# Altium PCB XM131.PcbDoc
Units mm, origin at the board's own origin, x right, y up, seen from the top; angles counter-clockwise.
Board outline 18.6 x 15 mm, 4 copper layers (Layer 1, Layer 2, Layer 3, Layer 4), stack 1.035 mm thick; 23 components, 34 nets, 164 pads, 93 vias.
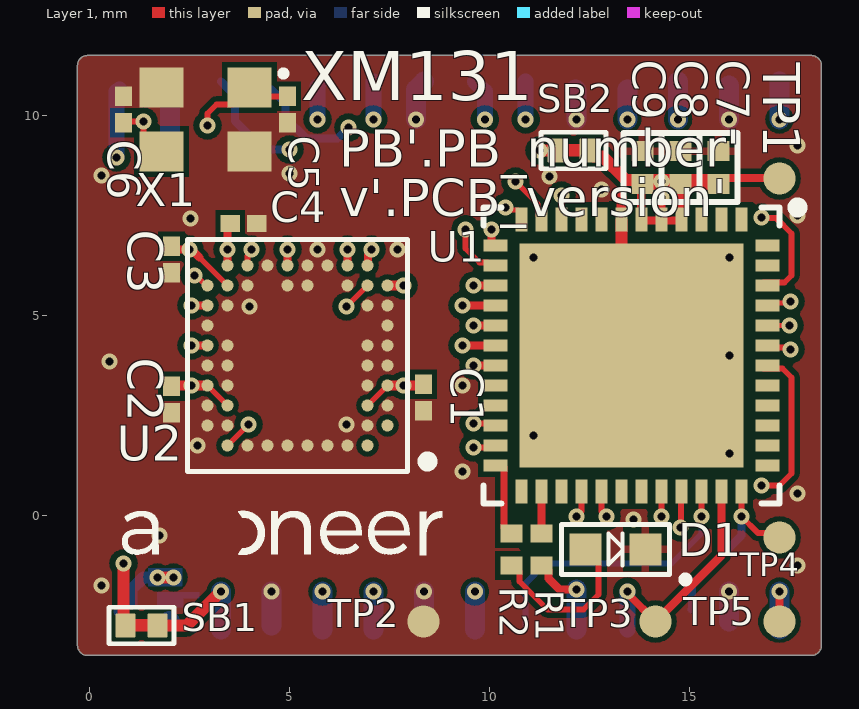
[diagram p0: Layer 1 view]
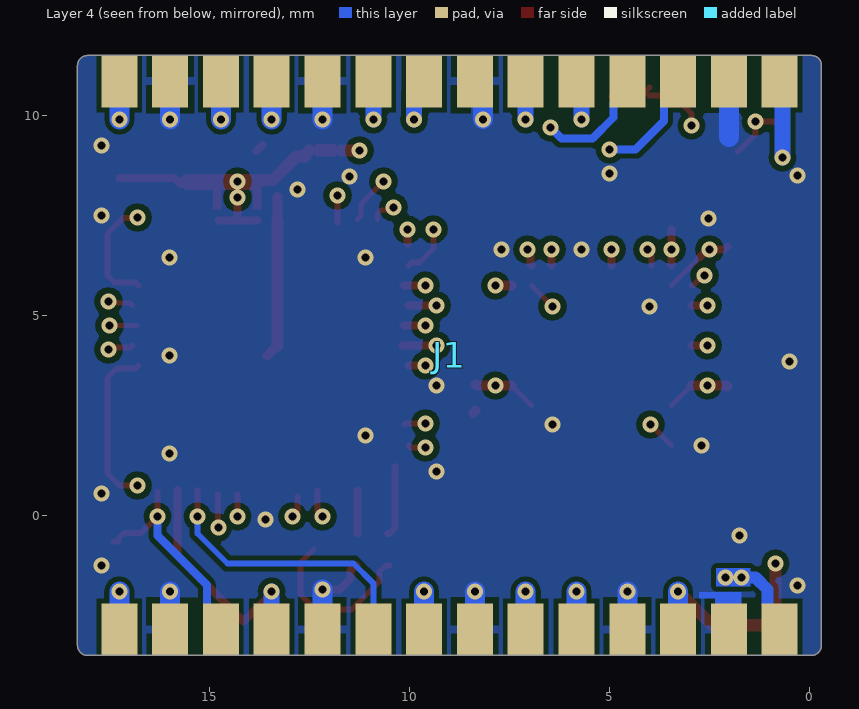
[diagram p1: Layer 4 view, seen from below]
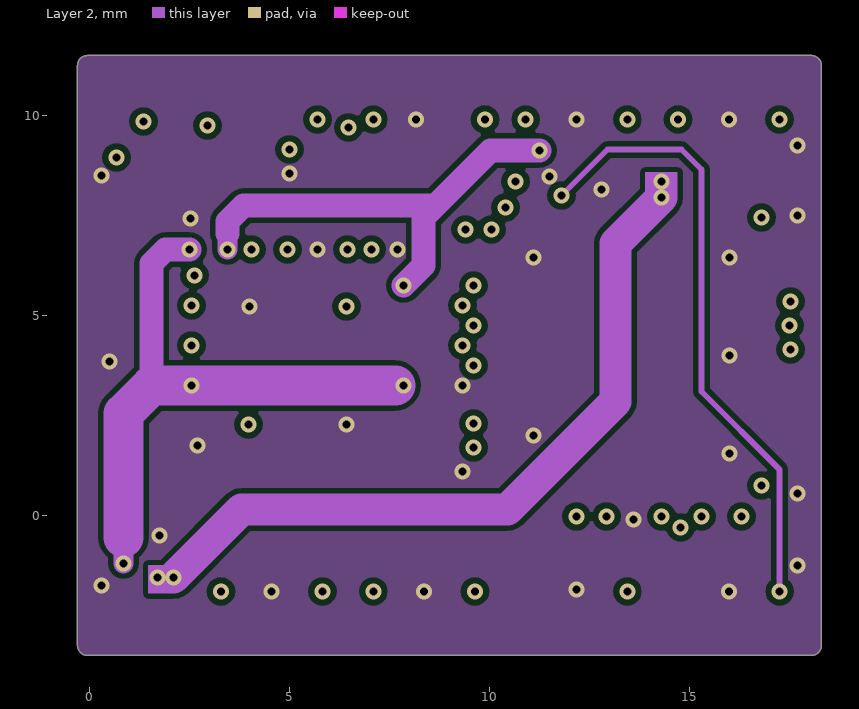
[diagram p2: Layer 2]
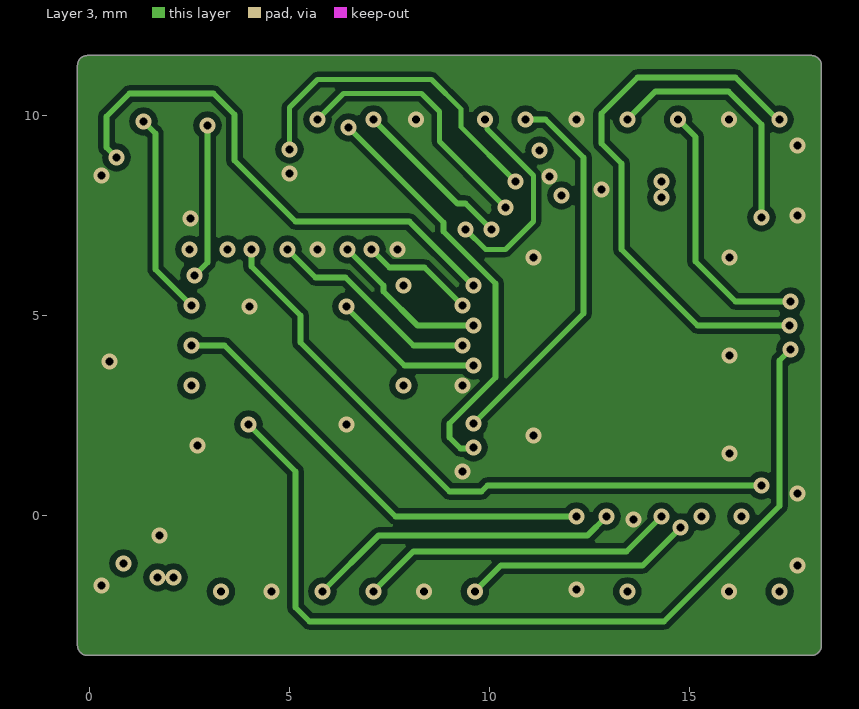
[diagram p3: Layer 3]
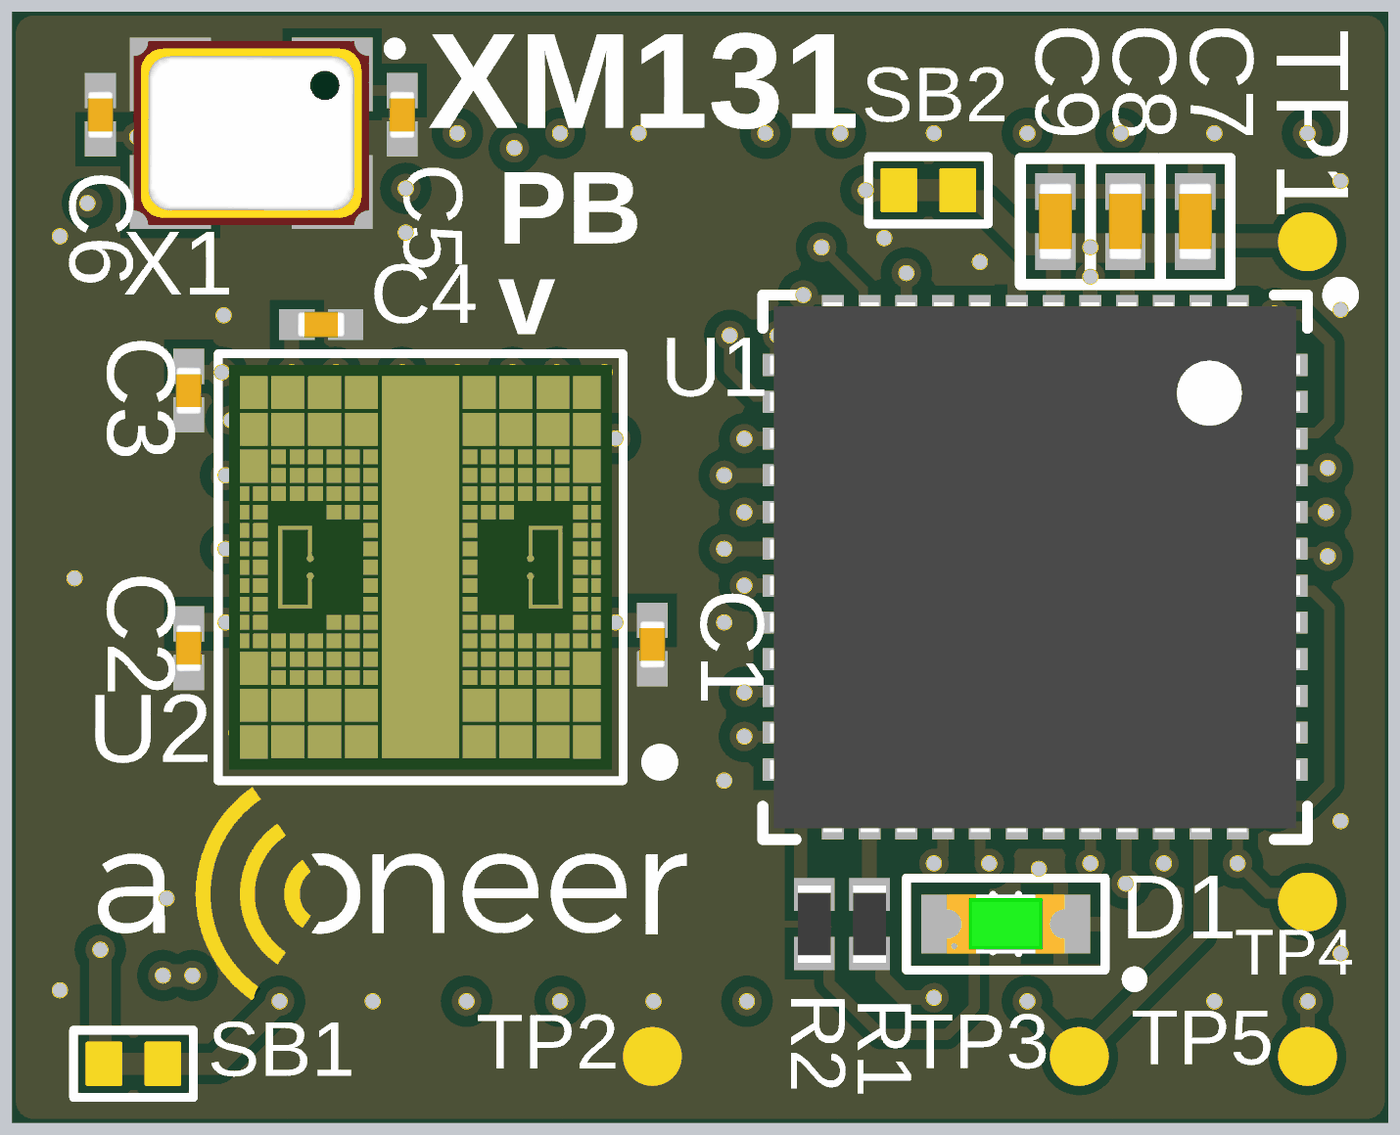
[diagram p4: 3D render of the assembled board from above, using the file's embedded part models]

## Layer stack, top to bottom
Top Solder: solder mask 0.0127, Solder Resist, Dk 3.5
Layer 1: signal copper 0.0175
Dielectric 1: prepreg 0.2, FR-4, Dk 4.05
Layer 2: signal copper 0.0175
Dielectric2: core 0.565, FR-4, Dk 4.6
Layer 3: signal copper 0.0175
Dielectric3: prepreg 0.2, FR-4, Dk 4.05
Layer 4: signal copper 0.0175
Bottom Solder: solder mask 0.0127, Solder Resist, Dk 3.5

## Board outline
-0.3,-3.25 -0.3,11.25 cw(c-0.05,11.25) -0.05,11.5 18.05,11.5 cw(c18.05,11.25) 18.3,11.25 18.3,-3.25 cw(c18.05,-3.25) 18.05,-3.5 -0.05,-3.5 cw(c-0.05,-3.25)

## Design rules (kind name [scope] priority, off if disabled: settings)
Clearance [All] p1: gap=0.127 ignorepadtopadclearanceinfootprint=TRUE except(0: Fill-Text Poly-Text Region-Text; 0.1: Arc-Text Track-Text SMDPad-Text THPad-Text Via-Text Text-Text; 0.15: SMDPad-Via THPad-Via Via-Fill Via-Poly Via-Region; 0.25: Arc-THPad Track-THPad SMDPad-THPad SMDPad-Hole THPad-Fill THPad-Poly THPad-Region Via-Hole Fill-Hole Poly-Hole Region-Hole; 0.254: THPad-Hole; 0.5: THPad-THPad)
ComponentClearance [All] p1: gap=0.2 collisioncheckmode=3 verticalgap=0.2 showdistances=FALSE
HoleSize [All] p1: absolutevalues=TRUE maxlimit=2.54 minlimit=0.2 maxpercent=80.000 minpercent=20.000
HoleToHoleClearance [All] p1: gap=0.1 allowstackedmicrovias=FALSE
MinimumSolderMaskSliver [All] p1: minsoldermaskwidth=0.1
NetAntennae [All] p1 off: netantennaetolerance=0
PolygonConnect PolygonConnect_A111_decoupling [HasFootprint('CAPC0603X04N_no_silkscreen') And OnLayer('Layer 1')] p1: thpad.connectstyle=Relief thpad.reliefconductorwidth=0.254 thpad.reliefentries=4 thpad.polygonreliefangle="90 Angle" thpad.airgapwidth=0.254 smdpad.connectstyle=Direct smdpad.reliefconductorwidth=0.254 smdpad.reliefentries=4 smdpad.polygonreliefangle="90 Angle" smdpad.airgapwidth=0.254 via.connectstyle=Relief via.reliefconductorwidth=0.254 via.reliefentries=4 via.polygonreliefangle="90 Angle" via.airgapwidth=0.254
PolygonConnect PolygonConnect_XTAL [HasFootprint('XTAL_320X260_no_silkscreen') And OnLayer('Layer 1')] p2: thpad.connectstyle=Relief thpad.reliefconductorwidth=0.254 thpad.reliefentries=4 thpad.polygonreliefangle="90 Angle" thpad.airgapwidth=0.254 smdpad.connectstyle=Direct smdpad.reliefconductorwidth=0.254 smdpad.reliefentries=4 smdpad.polygonreliefangle="90 Angle" smdpad.airgapwidth=0.254 via.connectstyle=Relief via.reliefconductorwidth=0.254 via.reliefentries=4 via.polygonreliefangle="90 Angle" via.airgapwidth=0.254
PolygonConnect PolygonConnect_A111 [HasFootprint('BGA50C50P10X10_520X550X90') And OnLayer('Layer 1')] p3: thpad.connectstyle=Relief thpad.reliefconductorwidth=0.254 thpad.reliefentries=4 thpad.polygonreliefangle="90 Angle" thpad.airgapwidth=0.254 smdpad.connectstyle=Direct smdpad.reliefconductorwidth=0.254 smdpad.reliefentries=4 smdpad.polygonreliefangle="90 Angle" smdpad.airgapwidth=0.254 via.connectstyle=Relief via.reliefconductorwidth=0.254 via.reliefentries=4 via.polygonreliefangle="90 Angle" via.airgapwidth=0.254
PolygonConnect [All] p4: connectstyle=Relief reliefconductorwidth=0.2 reliefentries=4 polygonreliefangle="90 Angle" airgapwidth=0.15
RoutingVias [All] p1: holewidth=0.2 width=0.45 viastyle="Through Hole" minholewidth=0.2 minwidth=0.4 maxholewidth=0.5 maxwidth=0.45
SilkToSilkClearance [All] p1: silktosilkclearance=0.1
SilkToSolderMaskClearance [IsPad] p1: minsilkscreentomaskgap=0.05 clearancetoexposedcopper=TRUE
SolderMaskExpansion [All] p1: expansion=0 istentingtop=FALSE useseparateexpansions=TRUE expansionbottom=0 istentingbottom=FALSE
Width Width_power [InNetClass('Power')] p1: maxlimit=1 minlimit=0.127 preferedwidth=0.5 midlayer1_minwidth=0.3 midlayer2_minwidth=0.3 bottomlayer_minwidth=0.3 minimp=50.000000 maximp=50.000000 favimp=50.000000
Width [All] p2: maxlimit=1 minlimit=0.127 preferedwidth=0.15 minimp=50.000000 maximp=50.000000 favimp=50.000000
23 further rules are at their usual default settings.

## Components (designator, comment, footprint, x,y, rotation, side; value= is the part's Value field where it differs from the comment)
C1 "Capacitor 1uF, metric 0603" CAPC0603X04N_no_silkscreen 8.35,2.95 r270 top value=1µF
C2 "Capacitor 1uF, metric 0603" CAPC0603X04N_no_silkscreen 2.05,2.9 r270 top value=1µF
C3 "Capacitor 1uF, metric 0603" CAPC0603X04N_no_silkscreen 2.05,6.4 r270 top value=1µF
C4 "Capacitor 1uF, metric 0603" CAPC0603X04N_no_silkscreen 3.85,7.3 r0 top value=1µF
C5 "Capacitor 8pF, metric 0603" CAPC0603X04N_no_silkscreen 4.95,10.15 r270 top value=8pF
C6 "Capacitor 8pF, metric 0603" CAPC0603X04N_no_silkscreen 0.85,10.15 r90 top value=8pF
C7 "Capacitor 4.7uF, metric 1005" CAPC1005X05L 15.725,8.7 r90 top value=4.7µF
C8 "Capacitor 4.7uF, metric 1005" CAPC1005X05L 14.775,8.7 r90 top value=4.7µF
C9 "Capacitor 100nF, metric 1005" CAPC1005X05L 13.825,8.7 r90 top value=100nF
D1 "LED, metric 1608" DIOC1608X04L(green) 13.15,-0.85 r180 top
J1 "XM131 28-pin LGA" LCCS127P1500X1800X0-28N 9,4 r90 bottom locked
R1 "Resistor 0 Ohm, metric 1005" RESC1005X04L 11.3,-0.85 r90 top value="0 Ohm"
R2 "Resistor 340 Ohm, metric 1005" RESC1005X04L 10.55,-0.85 r90 top value=240Ohm
SB1 "Solder Bridge" "Solder Bridge-Footprint-1" 1.3,-2.75 r180 top net-tie
SB2 "Solder Bridge" "Solder Bridge-Footprint-1" 12.1,9.125 r180 top net-tie
TP1 "Testpoint" Testpoint_circular_0.8_no_silkscreen#1 17.2,8.425 r90 top
TP2 "Testpoint" Testpoint_circular_0.8_no_silkscreen#2 8.35,-2.85 r90 top
TP3 "Testpoint" Testpoint_circular_0.8_no_silkscreen#2 14.15,-2.85 r90 top
TP4 "Testpoint" Testpoint_circular_0.8_no_silkscreen#3 17.25,-0.55 r90 top
TP5 "Testpoint" Testpoint_circular_0.8_no_silkscreen#2 17.25,-2.85 r90 top
U1 "STM32G071CBU6" QFN50P700X700X60_HS-49L 13.55,4 r270 top
U2 "A111-002" BGA50C50P10X10_520X550X90 5.2,4 r180 top locked
X1 "FL2400097" XTAL_320X260_no_silkscreen 2.9,9.9 r180 top

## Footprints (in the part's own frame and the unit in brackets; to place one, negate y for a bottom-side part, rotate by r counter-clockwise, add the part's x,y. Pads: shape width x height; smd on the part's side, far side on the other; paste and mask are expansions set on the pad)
BGA50C50P10X10_520X550X90 [mm]
  round 0.3 smd paste-0.05 mask+0.05: A2(-1.75,2.25) A3(-1.25,2.25) A4(-0.75,2.25) A5(-0.25,2.25) A6(0.25,2.25) A7(0.75,2.25) A8(1.25,2.25) A9(1.75,2.25) B1(-2.25,1.75) B2(-1.75,1.75) B9(1.75,1.75) B10(2.25,1.75) C1(-2.25,1.25) C2(-1.75,1.25) C9(1.75,1.25) C10(2.25,1.25) D1(-2.25,0.75) D2(-1.75,0.75) D9(1.75,0.75) D10(2.25,0.75) E1(-2.25,0.25) E2(-1.75,0.25) E9(1.75,0.25) E10(2.25,0.25) F1(-2.25,-0.25) F2(-1.75,-0.25) F9(1.75,-0.25) F10(2.25,-0.25) G1(-2.25,-0.75) G10(2.25,-0.75) H1(-2.25,-1.25) H2(-1.75,-1.25) H9(1.75,-1.25) H10(2.25,-1.25) J1(-2.25,-1.75) J2(-1.75,-1.75) J3(-1.25,-1.75) J5(-0.25,-1.75) J6(0.25,-1.75) J8(1.25,-1.75) J9(1.75,-1.75) J10(2.25,-1.75) K2(-1.75,-2.25) K3(-1.25,-2.25) K4(-0.75,-2.25) K5(-0.25,-2.25) K6(0.25,-2.25) K7(0.75,-2.25) K8(1.25,-2.25) K9(1.75,-2.25)
  silkscreen extent -3.37,-2.9 2.75,2.9, body extent -2.6,-2.75 2.6,2.75, height 0.51
CAPC0603X04N_no_silkscreen [mm] "Chip Capacitor, 2-Leads, Body 0.60x0.30mm, IPC Medium Density, no silkscreen"
  rect 0.48x0.42 smd: 1(-0.33,0) 2(0.33,0)
  body extent -0.33,-0.18 0.33,0.18, height 0.35
CAPC1005X05L [mm] "Chip Capacitor, 2-Leads, Body 1.00x0.50mm, IPC High Density"
  rect 0.5x0.55 smd: 1(-0.41,0) 2(0.41,0)
  silkscreen extent -0.86,-0.48 0.86,0.48, body extent -0.53,-0.23 0.53,0.23, height 0.5
DIOC1608X04L(green) [mm] "Chip Diode, 2-Leads, Body 1,60x0,80mm, IPC High Density"
  rect 0.8x0.8 smd: 1(-0.75,0) 2(0.75,0)
  silkscreen extent -1.8,-0.63 1.35,0.8, body extent -0.8,-0.4 0.8,0.4, height 0.6
LCCS127P1500X1800X0-28N [mm] "LCC, 28-Pins, Body 15.00x18.00 mm, Pitch 1.27mm"
  rect 1.3x0.9 smd paste-5: 1(-6.85,-8.255) 2(-6.85,-6.985) 3(-6.85,-5.715) 4(-6.85,-4.445) 5(-6.85,-3.175) 6(-6.85,-1.905) 7(-6.85,-0.635) 8(-6.85,0.635) 9(-6.85,1.905) 10(-6.85,3.175) 11(-6.85,4.445) 12(-6.85,5.715) 13(-6.85,6.985) 14(-6.85,8.255) 15(6.85,8.255) 16(6.85,6.985) 17(6.85,5.715) 18(6.85,4.445) 19(6.85,3.175) 20(6.85,1.905) 21(6.85,0.635) 22(6.85,-0.635) 23(6.85,-1.905) 24(6.85,-3.175) 25(6.85,-4.445) 26(6.85,-5.715) 27(6.85,-6.985) 28(6.85,-8.255)
QFN50P700X700X60_HS-49L [mm] "QFN, 48-Leads, Body 7,00x7,00mm, Pitch 0,50mm, Thermal Pad 5,60x5,60mm, IPC High Density"
  rect 0.6x0.3 smd: 1(-3.4,2.75) 2(-3.4,2.25) 3(-3.4,1.75) 4(-3.4,1.25) 5(-3.4,0.75) 6(-3.4,0.25) 7(-3.4,-0.25) 8(-3.4,-0.75) 9(-3.4,-1.25) 10(-3.4,-1.75) 11(-3.4,-2.25) 12(-3.4,-2.75) 25(3.4,-2.75) 26(3.4,-2.25) 27(3.4,-1.75) 28(3.4,-1.25) 29(3.4,-0.75) 30(3.4,-0.25) 31(3.4,0.25) 32(3.4,0.75) 33(3.4,1.25) 34(3.4,1.75) 35(3.4,2.25) 36(3.4,2.75)
  rect 0.3x0.6 smd: 13(-2.75,-3.4) 14(-2.25,-3.4) 15(-1.75,-3.4) 16(-1.25,-3.4) 17(-0.75,-3.4) 18(-0.25,-3.4) 19(0.25,-3.4) 20(0.75,-3.4) 21(1.25,-3.4) 22(1.75,-3.4) 23(2.25,-3.4) 24(2.75,-3.4) 37(2.75,3.4) 38(2.25,3.4) 39(1.75,3.4) 40(1.25,3.4) 41(0.75,3.4) 42(0.25,3.4) 43(-0.25,3.4) 44(-0.75,3.4) 45(-1.25,3.4) 46(-1.75,3.4) 47(-2.25,3.4) 48(-2.75,3.4)
  rect 5.6x5.6 smd paste-20: 49(0,0)
  silkscreen extent -3.82,-3.7 3.7,4.28, body extent -3.6,-3.6 3.6,3.6, height 0.6
RESC1005X04L [mm] "Chip Resistor, 2-Leads, Body 1,00x0,50mm, IPC High Density"
  rect 0.45x0.55 smd: 1(-0.4,0) 2(0.4,0)
  body extent -0.53,-0.23 0.53,0.23, height 0.4
"Solder Bridge-Footprint-1" [mm]
  rrect10% 0.5x0.6 smd paste-5: 1(-0.4,0) 2(0.4,0)
  Layer 1 region: -0.254,0.15 0.254,0.15 0.254,-0.15 -0.254,-0.15
  silkscreen extent -0.81,-0.46 0.81,0.46
Testpoint_circular_0.8_no_silkscreen#1 [mm]
  round 0.8 smd paste-5: 1(0,-0.05)
Testpoint_circular_0.8_no_silkscreen#2 [mm]
  round 0.8 smd paste-5: 1(0.2,0)
Testpoint_circular_0.8_no_silkscreen#3 [mm]
  round 0.8 smd paste-5: 1(0,0)
XTAL_320X260_no_silkscreen [mm] "XTAL, 4-Leads, Body 3.2x2.6mm, IPC High Density"
  rect 1.1x1 smd: 1(-1.1,-0.8) 2(1.1,-0.8) 3(1.1,0.8) 4(-1.1,0.8)
  silkscreen extent -2,-1.2 -1.9,-1.1, body extent -1.6,-1.25 1.6,1.25, height 0.82

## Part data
C1 C2 C3 C4: library part CMP-001-00106-6, "Generic 1uF SMD capacitor, metric 0603 (0201)", Case Code (Imperial)=0201, Case Code (Metric)=0603, Max Operating Temperature=85, Min Operating Temperature=-40, Tolerance=20%, Voltage Rating=6.3V
C5 C6: library part CMP-001-00107-4, "Generic 8pF SMD capacitor, metric 0603 (0201)", Capacitor Type=Ceramic, Case Code (Imperial)=0201, Case Code (Metric)=0603, Max Operating Temperature=85, Min Operating Temperature=-40, Temperature Coefficient="C0G, NP0", Tolerance=10%, Voltage Rating=25V
C7 C8: library part CMP-001-00105-4, "Generic 4.7uF SMD capacitor, metric 1005 (0402)", Case Code (Imperial)=0402, Case Code (Metric)=1005, Max Operating Temperature=85, Min Operating Temperature=-40, Voltage Rating=6.3V
C9: library part CMP-001-00083-20, "Generic 100nF SMD capacitor, metric 1005 (0402)", Case Code (Imperial)=0402, Case Code (Metric)=1005, Max Operating Temperature=85, Min Operating Temperature=-40, Tolerance=20%, Voltage Rating=6.3V
D1: library part CMP-004-00037-3, "Generic LED, metric 1608"
J1: library part CMP-002-00117-33, "XM131 28-pin Land Grid Array (LGA), pitch 1.27 mm"
R1: library part CMP-009-00186-15, "0 Ohm generic SMD resistor, +/-1%, metric 1005 (0402)", Max Operating Temperature=155°C, Min Operating Temperature=-55°C, Package (imperial)=0402, Package (metric)=1005, Rating=1%
R2: library part CMP-009-00208-8, "340 Ohm generic SMD resistor, +/-1%, metric 1005 (0402)", Max Operating Temperature=155°C, Min Operating Temperature=-55°C, Package (imperial)=0402, Package (metric)=1005, Rating=1%
SB1 SB2: library part CMP-002-00092-19, "Shorted Solder Bridge."
TP1 TP2 TP3 TP4 TP5: library part CMP-00030-00001-9, "Circular test point"
U1: library part CMP-020-00027-6, "STM32G Series 128 KB Flash 36 kB RAM 64 MHz 32-Bit Microcontroller - UFQFPN-48", Manufacturer=ST
U2: library part CMP-010-00029-2, "Acconeer A111-002 pulsed coherent 60 GHz radar sensor", Manufacturer="Acconeer AB", Max Operating Temperature=85°C, Min Operating Temperature=-40°C, Package=fcCSP50, Package Size="5.2 x 5.5 x 0.88 mm"
X1: library part CMP-003-00035-9, "Crystal 24MHz 9pF 4-Pin SMD", Case/Package=4-SMD, Frequency=24MHz, Load Capacitance=9pF, Manufacturer="Diodes Incorporated", Max Operating Temperature=85°C, Min Operating Temperature=-40°C

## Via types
v1: diameter 0.4, hole 0.2, Layer 1 to Layer 4, tented both sides, 93 vias

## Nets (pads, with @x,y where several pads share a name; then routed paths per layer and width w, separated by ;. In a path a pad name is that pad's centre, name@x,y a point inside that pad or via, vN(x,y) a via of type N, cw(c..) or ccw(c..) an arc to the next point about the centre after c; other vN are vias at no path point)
1V8: J1.3 SB1.1 | length 2.9
  Layer 1 w0.3: SB1.1 2.435,-2.75 v1(3.285,-1.9)
  Layer 4 w0.5: J1.3 v1(3.285,-1.9)
1V8_sensor: C1.1 C2.1 C3.1 SB1.2 U2.C2 U2.C9 U2.D1 U2.D10 U2.J9 | length 21.5
  Layer 1 w0.127: 2.75,6.45 U2.J9 ; U2.D10 U2.C9 ; U2.C2 U2.D1
  Layer 1 w0.2: C3.1 2.13,6.65 v1(2.5,6.65) 2.55,6.65 2.75,6.45
  Layer 1 w0.25: C2.1 2.07,3.25 v1(2.55,3.25) U2.D10 ; U2.D1 v1(7.85,3.25) 8.32,3.25 C1.1
  Layer 1 w0.3: SB1.2@0.85,-2.75 v1@0.85,-1.25
  Layer 2 w0.5: v1(0.85,-1.2) 0.85,-0.55
  Layer 2 w0.6: 1.55,3.25 1.55,6.299 1.901,6.65 v1(2.5,6.65)
  Layer 2 w1: 0.85,-0.55 0.85,2.55 1.55,3.25 v1(2.55,3.25) v1@7.65,3.25
CTRL: U1.43 U2.A9 | length 23.9
  Layer 1 w0.127: U2.A9 v1(3.975,2.275)
  Layer 1 w0.15: U1.43@16.925,4.25 16.975,4.2 17.357,4.2 17.457,4.1 v1@17.5,4.1
  Layer 3 w0.15: v1(3.975,2.275) 5.15,1.1 5.15,-2.3 5.5,-2.65 14.362,-2.65 17.25,0.238 17.25,3.875 v1(17.525,4.15)
DEBUG_UART_RX: J1.21 U1.14 | length 7.6
  Layer 1 w0.15: v1(9.402,7.152) 9.4,7.15 9.4,6.675 9.75,6.325 9.95,6.325 U1.14@10.025,6.25
  Layer 3 w0.127: v1(9.402,7.152) 9.904,6.65 10.4,6.65 11.1,7.35 11.1,8.5 9.937,9.663 9.937,9.848 v1(9.885,9.9)
  Layer 4 w0.4: J1.21 9.885,10.6 v1(9.885,9.9)
DEBUG_UART_TX: J1.23 U1.13 | length 5.4
  Layer 1 w0.2: U1.13@10.05,6.8 v1(10.05,7.15)
  Layer 3 w0.15: v1(7.095,9.9) 9.195,7.8 9.4,7.8 v1(10.05,7.15)
  Layer 4 w0.4: v1(7.095,9.9) J1.23
ENABLE: U1.28 U2.F10 | length 12.5
  Layer 1 w0.15: v1(12.175,-0.025) 12.3,0.1 12.3,0.3 U1.28@12.3,0.625
  Layer 1 w0.2: v1(2.55,4.25) U2.F10
  Layer 3 w0.15: v1(2.55,4.25) 3.375,4.25 7.65,-0.025 v1(12.175,-0.025)
GND: C1.2 C2.2 C3.2 C4.2 C5.2 C6.2 C7.2 C8.2 C9.2 D1.1 J1.2 J1.4 J1.7 J1.10 J1.13 J1.16 J1.19 J1.22 J1.27 R1.1 TP2.1 U1.7 U1.49 U2.A3 U2.A4 U2.A5 U2.A6 U2.A7 U2.A8 U2.B2 U2.B9 U2.B10 U2.C1 U2.C10 U2.D2 U2.D9 U2.E1 U2.E2 U2.E9 U2.E10 U2.F1 U2.F2 U2.F9 U2.G1 U2.G10 U2.H1 U2.H2 U2.H9 U2.J3 U2.J5 U2.J6 U2.J8 U2.K4 U2.K5 U2.K7 X1.2 X1.4 | length 12.2
  Layer 1 w0.2: R1.1@11.325,-1.25 11.35,-1.25 11.475,-1.375 11.475,-1.575 11.75,-1.85 12.173,-1.85 v1(12.175,-1.852) ; C9.2@13.675,9.26 C9.2
  Layer 1 w0.25: U1.49@13.3,4.25 U1.49 ; U1.7@13.3,7.375 U1.7 13.3,7.959
  Layer 1 w0.254: C1.2 C1.2@8.4,2.57
  Layer 1 w0.3: U1.49@13.3,4.25 U1.7@13.3,7.375
  Layer 4 w0.5: J1.2@2,-2.635 J1.2@2.015,-2.65 ; 2.015,9.465 J1.27@2.015,10.4 ; J1.4@4.555,-2.75 v1@4.555,-1.9 ; v1@8.165,9.915 8.165,10.65 J1.22 ; J1.7@8.365,-2.4 v1(8.365,-1.9) ; J1.19@12.15,10.65 12.175,10.625 v1(12.175,9.9) ; J1.10 v1(12.175,-1.852) ; J1.13@15.985,-2.65 v1(15.985,-1.9) ; v1(15.985,9.9) J1.16@15.985,10.75
  other v1: 4.55,-1.9 0.3,-1.75 17.7,-1.25 1.75,-0.5 13.6,-0.1 17.7,0.55 9.325,1.1 16,1.55 2.7,1.75 11.1,2 6.425,2.275 9.325,3.25 0.5,3.85 16,4 4,5.225 11.1,6.45 16,6.45 5.7,6.65 7.7,6.65 2.525,7.425 17.7,7.5 12.8,8.15 11.5,8.475 0.3,8.5 5,8.55 17.7,9.25 8.165,9.9
I2C_ADDR: J1.20 U1.22 | length 11.1
  Layer 1 w0.15: v1(9.6,2.3) 10.1,2.3 U1.22@10.125,2.275
  Layer 3 w0.15: v1(9.6,2.3) 12.35,5.05 12.35,8.95 11.4,9.9 v1(10.905,9.9)
  Layer 4 w0.4: v1(10.905,9.9) J1.20
I2C_SCL: J1.17 U1.45 | length 8.1
  Layer 1 w0.127: U1.45@16.925,5.25 16.986,5.312 17.363,5.312 17.451,5.4 v1@17.5,5.4
  Layer 3 w0.15: v1(14.715,9.9) 15.15,9.465 15.15,6.35 16.15,5.35 v1(17.525,5.35)
  Layer 4 w0.5: v1(14.715,9.9) J1.17
I2C_SDA: J1.18 U1.46 | length 9.9
  Layer 1 w0.15: U1.46@16.775,5.75 16.85,5.825 17.375,5.825 17.55,6 17.55,7.05 17.168,7.432 16.818,7.432 v1(16.8,7.45)
  Layer 3 w0.15: v1(13.445,9.9) 14.145,10.6 15.975,10.6 16.8,9.775 v1(16.8,7.45)
  Layer 4 w0.5: v1(13.445,9.9) J1.18@13.445,10.645 ; J1.18@13.445,10.65 J1.18@13.45,10.645
INTERRUPT: U1.42 U2.K8 | length 20.6
  Layer 1 w0.15: U2.K8 3.95,6.482 4.05,6.582 v1(4.05,6.65) ; U1.42@16.775,3.75 16.85,3.675 17.325,3.675 17.55,3.45 17.55,1.05 17.25,0.75 v1(16.8,0.75)
  Layer 3 w0.15: v1(4.05,6.65) 4.05,6.225 5.275,5 5.275,4.325 9,0.6 9.8,0.6 9.95,0.75 v1(16.8,0.75)
MCU_INT: J1.28 U1.15 | length 15.5
  Layer 1 w0.2: v1@9.575,5.747 9.576,5.749 10.149,5.749 U1.15
  Layer 3 w0.15: v1(0.675,8.95) 0.425,9.2 0.425,9.975 1,10.55 3.1,10.55 3.625,10.025 3.625,8.875 5.15,7.35 7.997,7.35 v1(9.6,5.747)
  Layer 4 w0.4: v1(0.675,8.95) J1.28@0.675,10.605 ; J1.28@0.7,10.605 J1.28@0.745,10.65
MISC_GPIO0: J1.24 U1.12 | length 8.2
  Layer 1 w0.127: v1(10.4,7.7) 10.474,7.7 10.537,7.636 10.713,7.636 10.8,7.55 U1.12
  Layer 3 w0.127: v1(5.7,9.9) 6.35,10.55 8.3,10.55 8.75,10.1 8.75,9.35 v1(10.4,7.7)
  Layer 4 w0.3: J1.24@5.7,10.725 J1.24
  Layer 4 w0.4: v1(5.7,9.9) J1.24@5.7,10.725
MISC_GPIO1: J1.25 U1.23 | length 13.7
  Layer 1 w0.15: v1@9.55,1.65 v1(9.6,1.7) 9.975,1.7 U1.23@10.025,1.75
  Layer 3 w0.15: v1(6.475,9.7) 8.85,7.325 8.85,7.1 10.15,5.8 10.15,3.45 9,2.3 9,1.95 9.274,1.676 9.576,1.676 v1(9.6,1.7)
  Layer 4 w0.2: J1.25@4.555,10.65 4.905,10.3 4.905,9.945 5.425,9.425 6.2,9.425 v1(6.475,9.7)
MISC_GPIO2: J1.26 U1.11 | length 12.3
  Layer 1 w0.127: v1(10.649,8.349) 10.651,8.349 11.213,7.786 11.213,7.487 U1.11
  Layer 3 w0.127: v1(5,9.15) 5,10.2 5.7,10.9 8.55,10.9 9.292,10.158 9.292,9.708 10.649,8.351 v1(10.649,8.349)
  Layer 4 w0.2: J1.26 3.635,10.5 3.635,9.865 4.35,9.15 v1(5,9.15)
NetD1_2: D1.2 R2.1 | length 4.2
  Layer 1 w0.15: R2.1@10.5,-1.25 10.6,-1.25 10.75,-1.4 10.75,-1.65 11.45,-2.35 12.35,-2.35 12.725,-1.975 12.725,-1.175 D1.2
NetR1_2: R1.2 U1.26 | length 1.1
  Layer 1 w0.2: R1.2 U1.26@11.3,0.625
NetR2_2: R2.2 U1.24 | length 1.8
  Layer 1 w0.175: U1.24@10.35,1.225 10.362,1.212 10.362,-0.262 10.362,-0.313 10.5,-0.45 R2.2
NRESET: J1.14 TP5.1 U1.10 | length 17.9
  Layer 1 w0.15: U1.10@11.8,7.33 v1(11.8,8)
  Layer 1 w0.2: TP5.1 17.252,-2.648 17.252,-1.953 v1@17.255,-1.95
  Layer 2 w0.15: v1(11.8,8) 12.95,9.15 14.8,9.15 15.3,8.65 15.3,3.1 17.255,1.145 v1(17.255,-1.9)
  Layer 4 w0.5: J1.14 v1(17.255,-1.9)
SPI_CLK: U1.16 U2.K2 | length 4
  Layer 1 w0.2: U2.K2 6.969,6.269 6.969,6.515 7.05,6.596 v1(7.05,6.65) ; v1(9.325,5.25) U1.16@10.025,5.25
  Layer 3 w0.15: v1(7.05,6.65) 7.5,6.2 8.375,6.2 v1(9.325,5.25)
SPI_MISO: U1.17 U2.K3 | length 5
  Layer 1 w0.2: U2.K3 v1(6.45,6.65) ; v1@9.575,4.748 9.576,4.749 U1.17 U1.17
  Layer 3 w0.15: v1(6.45,6.65) 7.35,5.75 7.35,5.6 8.202,4.748 v1(9.6,4.748)
SPI_MOSI: U1.18 U2.K6 | length 6.6
  Layer 1 w0.2: U2.K6 v1(4.95,6.65) ; v1(9.325,4.25) U1.18@10.175,4.25
  Layer 3 w0.15: v1(4.95,6.65) 5.65,5.95 6.4,5.95 8.1,4.25 v1(9.325,4.25)
SPI_SS: U1.19 U2.J2 | length 5
  Layer 1 w0.127: v1(6.425,5.225) U2.J2
  Layer 1 w0.2: v1@9.598,3.752 9.599,3.751 U1.19@10.024,3.751 ; U1.19@10.024,3.751 U1.19@10.025,3.75
  Layer 3 w0.15: v1(6.425,5.225) 6.425,5.2 7.875,3.75 v1(9.6,3.75)
SWDCLK_BOOT0: J1.12 TP4.1 U1.36 | length 4.8
  Layer 1 w0.15: U1.36 v1(16.3,-0.025) 16.708,-0.433 17.133,-0.433 TP4.1 ; TP4.1@17.275,-0.65 TP4.1@17.4,-0.65
  Layer 4 w0.2: J1.12@15.05,-2.35 15.065,-2.335 15.065,-1.735 16.3,-0.5 v1(16.3,-0.025)
SWDIO: J1.11 TP3.1 U1.35 | length 5.9
  Layer 1 w0.2: v1@13.467,-1.967 TP3.1 15.8,-1 U1.35@15.8,0.64
  Layer 4 w0.4: J1.11 v1(13.445,-1.9)
UART_CTS: J1.8 U1.33 | length 7.6
  Layer 1 w0.15: v1@14.78,-0.28 14.79,-0.271 14.79,0.512 U1.33@14.8,0.522
  Layer 3 w0.15: v1(9.635,-1.9) 10.285,-1.25 13.83,-1.25 v1(14.78,-0.3)
  Layer 4 w0.5: J1.8 v1(9.635,-1.9)
UART_RTS: J1.9 U1.34 | length 7
  Layer 1 w0.15: v1@15.3,0.05 U1.34@15.3,0.631
  Layer 4 w0.15: J1.9@10.905,-2.75 10.905,-1.695 11.4,-1.2 14.55,-1.2 15.3,-0.45 v1(15.3,-0.025)
UART_RX: J1.6 U1.32 | length 9.4
  Layer 1 w0.15: v1@14.3,0.05 U1.32@14.3,0.527
  Layer 3 w0.15: v1(7.095,-1.9) 8.095,-0.9 13.425,-0.9 v1(14.3,-0.025)
  Layer 4 w0.5: J1.6 v1(7.095,-1.9)
UART_TX: J1.5 U1.29 | length 9.4
  Layer 1 w0.15: U1.29@12.8,0.475 12.8,0.1 v1(12.925,-0.025)
  Layer 3 w0.15: v1(5.825,-1.9) 7.223,-0.502 12.448,-0.502 v1(12.925,-0.025)
  Layer 4 w0.5: J1.5 v1(5.825,-1.9)
VIN: C7.1 C8.1 C9.1 J1.1 SB2.1 TP1.1 U1.4 U1.5 U1.6 | length 27
  Layer 1 w0.2: U1.6@13.8,7.375 U1.5@14.3,7.375 ; v1@14.3,8.325 U1.5 U1.5@14.3,7.375 ; U1.4@14.775,7.375 U1.5@14.3,7.375 ; C7.1 15.875,8.44 TP1.1@17.25,8.44
  Layer 1 w0.3: v1(1.7,-1.55) v1(2.1,-1.55) ; SB2.1 12.6,9.025 12.6,8.975 12.825,8.975 13.41,8.39 13.725,8.39 C9.1
  Layer 1 w0.4: C9.1@13.825,8.34 C7.1@15.55,8.34
  Layer 2 w0.8: v1(2.1,-1.55) 3.8,0.15 10.45,0.15 13.15,2.85 13.15,6.8 v1(14.3,7.95)
  Layer 4 w0.3: J1.1@0.745,-2.4 J1.1@0.845,-2.4 ; 1.045,-2.2 1.045,-1.855 1.35,-1.55 v1(1.7,-1.55)
  other v1: 14.3,8.35
VIN_sensor: C4.1 SB2.2 U2.J1 U2.K9 | length 13.3
  Layer 1 w0.2: U2.K9 v1(3.45,6.65) C4.1@3.45,7.15
  Layer 1 w0.25: U2.J1 7.451,5.751 v1@7.801,5.751
  Layer 1 w0.3: v1@11.223,9.15 11.25,9.15 v1(11.25,9.125) SB2.2
  Layer 2 w0.5: v1(3.45,6.65) 3.45,7.05
  Layer 2 w0.6: 3.45,7.05 3.45,7.35 3.85,7.75 8.65,7.75 ; v1(7.85,5.75) 8.35,6.25 8.35,7.45 8.65,7.75 ; v1(11.25,9.125) 10.025,9.125 8.65,7.75
WAKE_UP: J1.15 U1.44 | length 15.3
  Layer 1 w0.127: U1.44@16.8,4.75 v1@17.35,4.75
  Layer 3 w0.15: v1(17.25,9.9) 17.2,9.9 16.15,10.95 13.7,10.95 12.8,10.05 12.8,9.3 13.3,8.8 13.3,6.65 15.2,4.75 v1(17.5,4.75)
  Layer 4 w0.5: v1(17.25,9.9) J1.15@17.25,10.845
XIN: C5.1 U2.J10 X1.1 | length 6.7
  Layer 1 w0.15: v1(2.625,6) 2.663,6 2.912,5.75 U2.J10 ; v1(2.95,9.75) 2.95,10.05 3.175,10.275 3.575,10.275 X1.1@3.6,10.3 ; X1.1@3.75,10.5 X1.1@4,10.5 ; X1.1 4.22,10.48 C5.1
  Layer 3 w0.15: v1(2.625,6) 2.95,6.325 v1(2.95,9.75)
XOUT: C6.1 U2.H10 X1.3 | length 7
  Layer 1 w0.14: C6.1 0.88,9.85 v1(1.35,9.85) 1.35,9.53 1.78,9.1 X1.3
  Layer 1 w0.2: v1(2.55,5.25) U2.H10
  Layer 3 w0.14: v1(1.35,9.85) 1.65,9.55 1.65,6.15 v1(2.55,5.25)
pads on no net: U1.1 U1.2 U1.3 U1.8 U1.9 U1.20 U1.21 U1.25 U1.27 U1.30 U1.31 U1.37 U1.38 U1.39 U1.40 U1.41 U1.47 U1.48 U2.A2 U2.B1

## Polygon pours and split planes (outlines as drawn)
GND on Layer 4 "GND_L04_P024" (solid, remove dead copper, pour order 24): -0.3,-3.25 -0.3,11.25 cw(c-0.05,11.25) -0.05,11.5 18.05,11.5 cw(c18.05,11.25) 18.3,11.25 18.3,-3.25 cw(c18.05,-3.25) 18.05,-3.5 -0.05,-3.5 cw(c-0.05,-3.25)
GND on Layer 3 "GND_L03_P025" (solid, remove dead copper, pour order 25): -0.3,-3.25 -0.3,11.25 cw(c-0.05,11.25) -0.05,11.5 18.05,11.5 cw(c18.05,11.25) 18.3,11.25 18.3,-3.25 cw(c18.05,-3.25) 18.05,-3.5 -0.05,-3.5 cw(c-0.05,-3.25)
GND on Layer 2 "GND_L02_P026" (solid, remove dead copper, pour order 26): -0.3,-3.25 -0.3,11.25 cw(c-0.05,11.25) -0.05,11.5 18.05,11.5 cw(c18.05,11.25) 18.3,11.25 18.3,-3.25 cw(c18.05,-3.25) 18.05,-3.5 -0.05,-3.5 cw(c-0.05,-3.25)
GND on Layer 1 "GND_L01_P027" (solid, remove dead copper, pour order 27): -0.3,-3.25 -0.3,11.25 cw(c-0.05,11.25) -0.05,11.5 18.05,11.5 cw(c18.05,11.25) 18.3,11.25 18.3,-3.25 cw(c18.05,-3.25) 18.05,-3.5 -0.05,-3.5 cw(c-0.05,-3.25)

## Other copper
Layer 1:
  pour cut-out: 4.25,10.65 4.25,10.634 4.38,10.504 4.15,10.274 4.15,10.25
  region net VIN: 13.7,7.65 13.7,8.15 13.9,8.15 13.9,7.65
  region net VIN: 14.7,7.65 14.7,8.15 14.9,8.15 14.9,7.65
Layer 2:
  region net VIN: 2.1,-1.25 1.475,-1.25 1.475,-1.95 2.1,-1.95
  region net VIN: 14.7,7.95 14.7,8.575 13.9,8.575 13.9,7.95
Layer 4:
  region net VIN: 2.325,-1.325 2.325,-1.775 1.475,-1.775 1.475,-1.325
  region net GND: 2.75,-2.075 2.35,-2.075 2.35,-2.3 1.7,-2.3 1.7,-1.925 2.75,-1.925

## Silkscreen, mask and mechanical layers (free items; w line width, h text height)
Top Overlay:
  drawing of 6 lines, arcs and shapes, not listed
  text "XM131" at 5.3,9.975 h2.1
  text "PB'.PB_number'" at 6.25,8.4 h1.6
  text "v'.PCB_version'" at 6.25,7.169 h1.6
Top Solder:
  drawing of 3 lines, arcs and shapes, not listed
Board Shape:
  the board outline again, w0.1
